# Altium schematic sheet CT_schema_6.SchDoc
size 391 x 238 mm
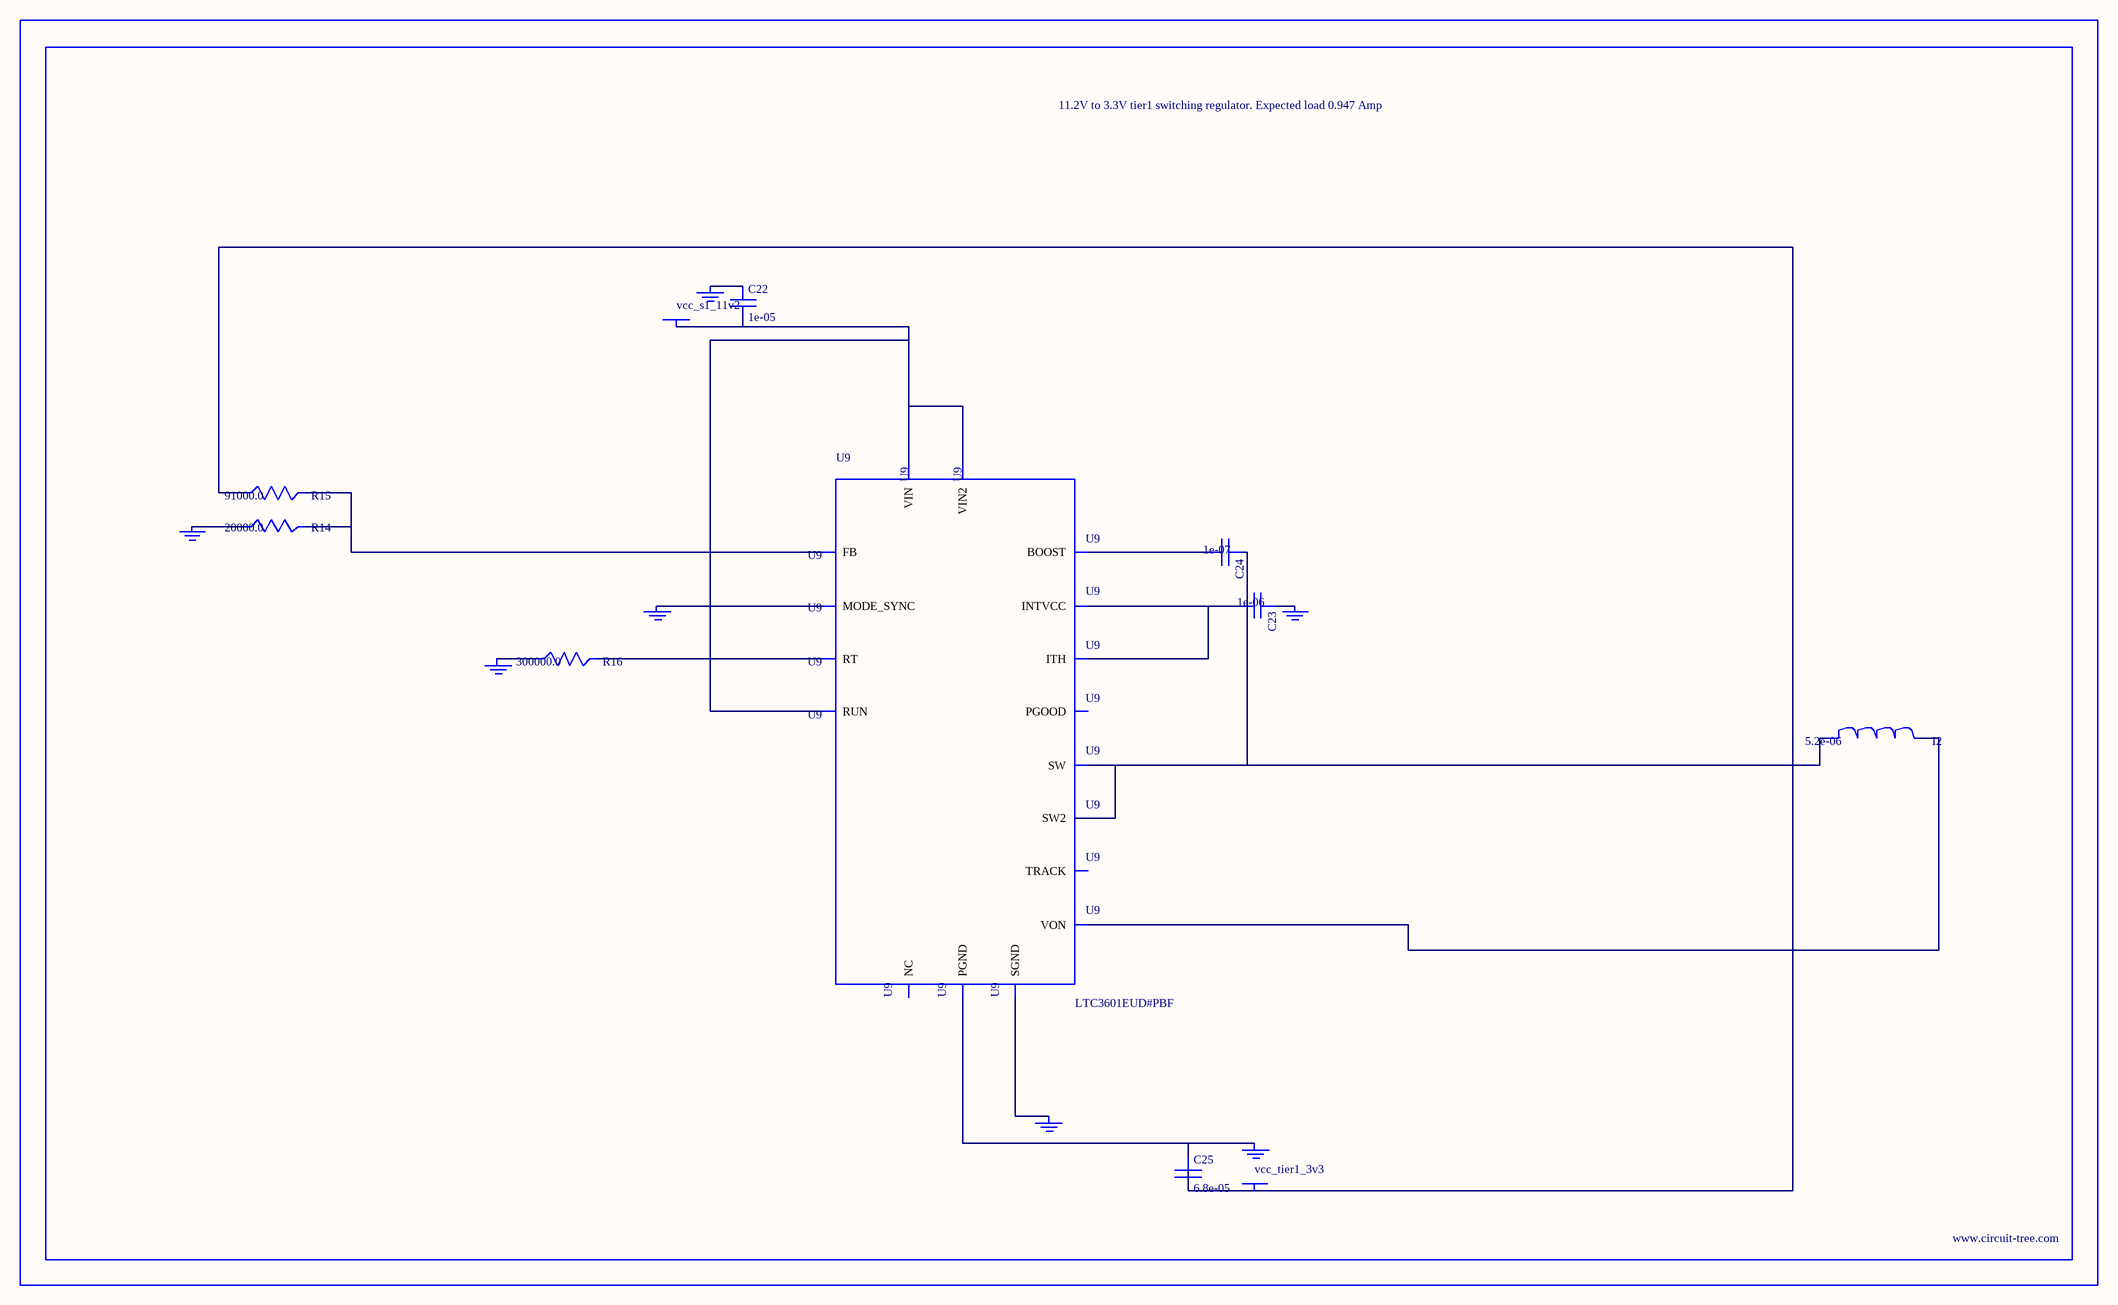
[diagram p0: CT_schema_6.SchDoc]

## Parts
BORDER5  (no value)
C22  1e-05  [C0805]
C23  1e-06  [C0603]
C24  1e-07  [C0402]
C25  6.8e-05  [2220]
GND_INSTANCE_5_0  (no value)
GND_INSTANCE_5_1  (no value)
GND_INSTANCE_5_2  (no value)
GND_INSTANCE_5_3  (no value)
GND_INSTANCE_5_4  (no value)
GND_INSTANCE_5_5  (no value)
GND_INSTANCE_5_6  (no value)
I2  5.2e-06  [DR1040]
POWER_INSTANCE_5_0  vcc_s1_11v2
POWER_INSTANCE_5_1  vcc_tier1_3v3
R14  20000.0  [R0603]
R15  91000.0  [R0603]
R16  300000.0  [R0603]
U9  LTC3601EUD#PBF  [QFN-16_EP]

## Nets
NetC22_1: C22.1 GND_INSTANCE_5_5.0(GND)
NetC22_2: C22.2 POWER_INSTANCE_5_0.0(PWR) U9.14(RUN) U9.15(VIN) U9.16(VIN2)
NetC23_1: C23.1 GND_INSTANCE_5_1.0(GND)
NetC23_2: C23.2 U9.7(INTVCC) U9.12(ITH)
NetC24_1: C24.1 I2.1 U9.3(SW) U9.4(SW2)
NetC24_2: C24.2 U9.6(BOOST)
NetC25_1: C25.1 GND_INSTANCE_5_6.0(GND) U9.17(PGND)
NetC25_2: C25.2 I2.2 POWER_INSTANCE_5_1.0(PWR) R15.1 U9.8(VON)
NetGND_INSTANCE_5_0_0: GND_INSTANCE_5_0.0(GND) U9.1(MODE_SYNC)
NetGND_INSTANCE_5_2_0: GND_INSTANCE_5_2.0(GND) U9.9(SGND)
NetGND_INSTANCE_5_3_0: GND_INSTANCE_5_3.0(GND) R16.1
NetGND_INSTANCE_5_4_0: GND_INSTANCE_5_4.0(GND) R14.1
NetR14_2: R14.2 R15.2 U9.11(FB)
NetR16_2: R16.2 U9.10(RT)

Not connected (* = marked no-connect by the designer): U9 2(PGOOD) 5(NC) 13(TRACK)

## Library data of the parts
BORDER5 = BORDER_PAGE5
C22 = C0805C106K8RACTU
C23 = C0603C105K3RACTU
C24 = C0402C104K3RACTU
C25 = C5750X5R1A686M
GND_INSTANCE_5_0-GND_INSTANCE_5_6 = GND
I2 = DR1040-5R2-R
POWER_INSTANCE_5_0 POWER_INSTANCE_5_1 = PWR
R14 = RC0603JR-0720KL
R15 = RC0603JR-0791KL
R16 = RC0603JR-07300KL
